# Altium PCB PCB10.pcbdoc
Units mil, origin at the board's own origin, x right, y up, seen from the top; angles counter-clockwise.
Board outline 3030 x 1495.29 mil, 6 copper layers (Top Layer, GND, Inner2, Inner3, 3.3, Bottom Layer); 71 components, 90 nets, 326 pads, 205 vias.
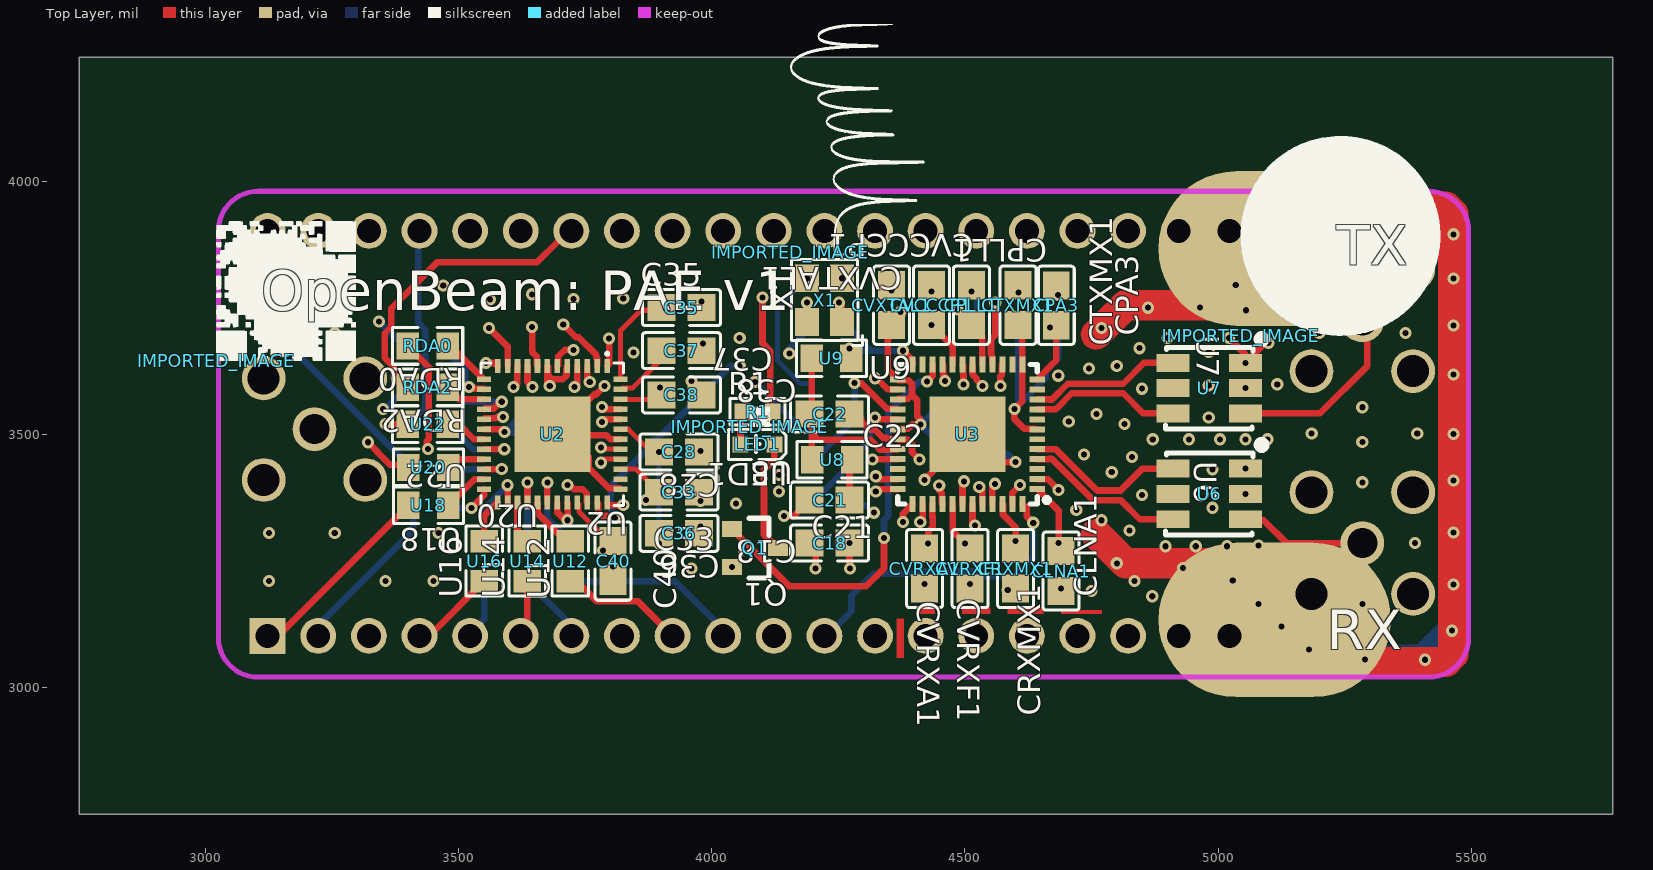
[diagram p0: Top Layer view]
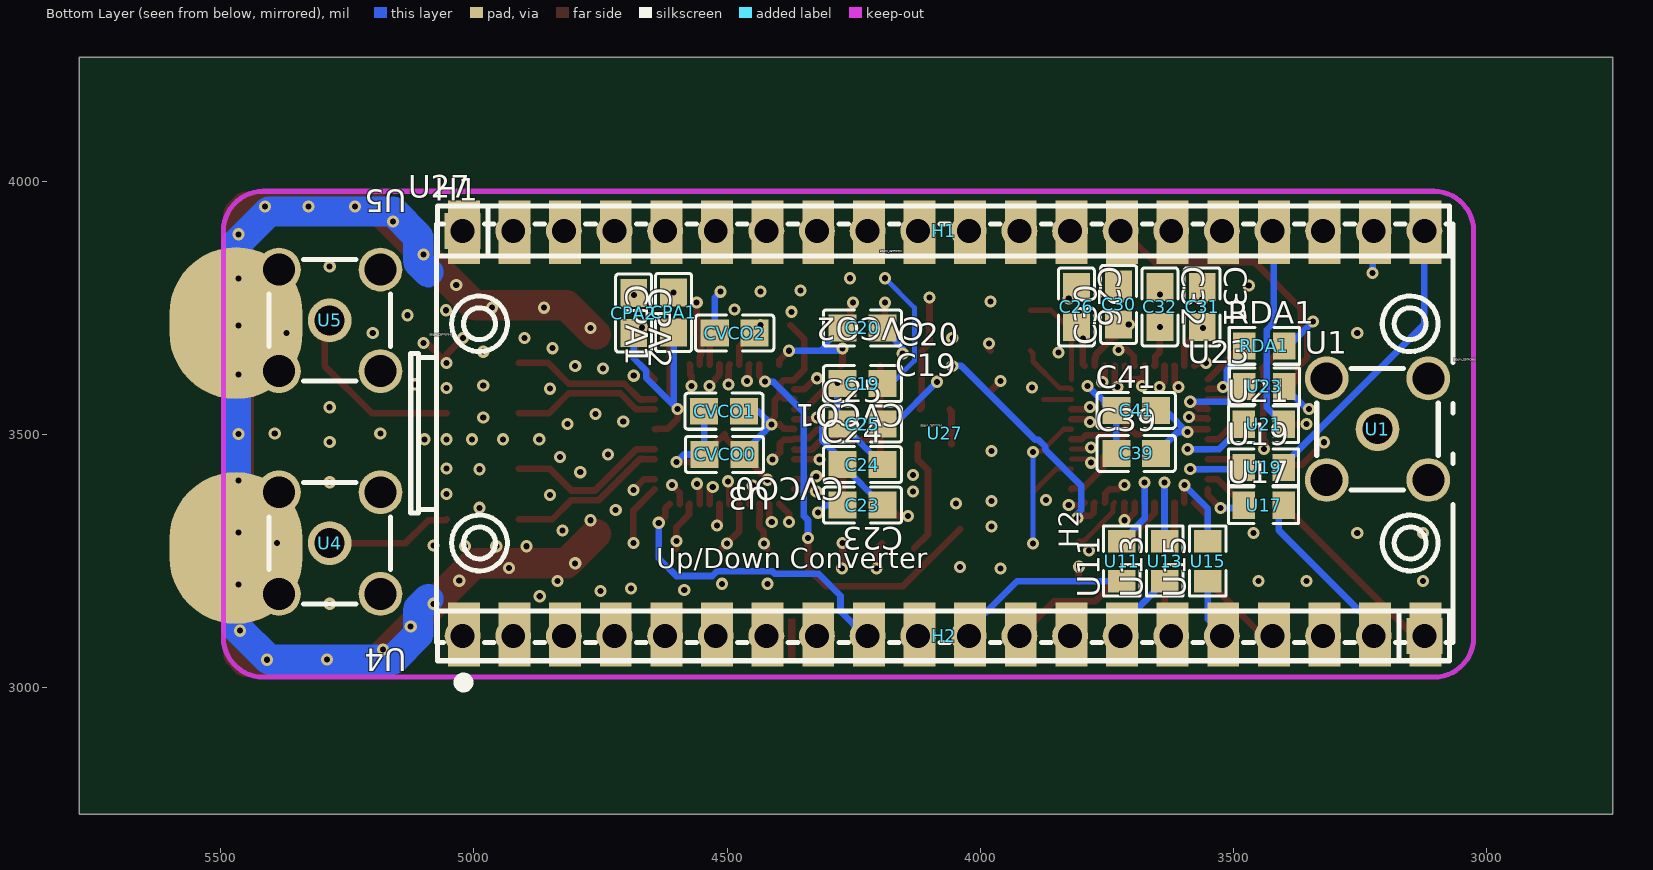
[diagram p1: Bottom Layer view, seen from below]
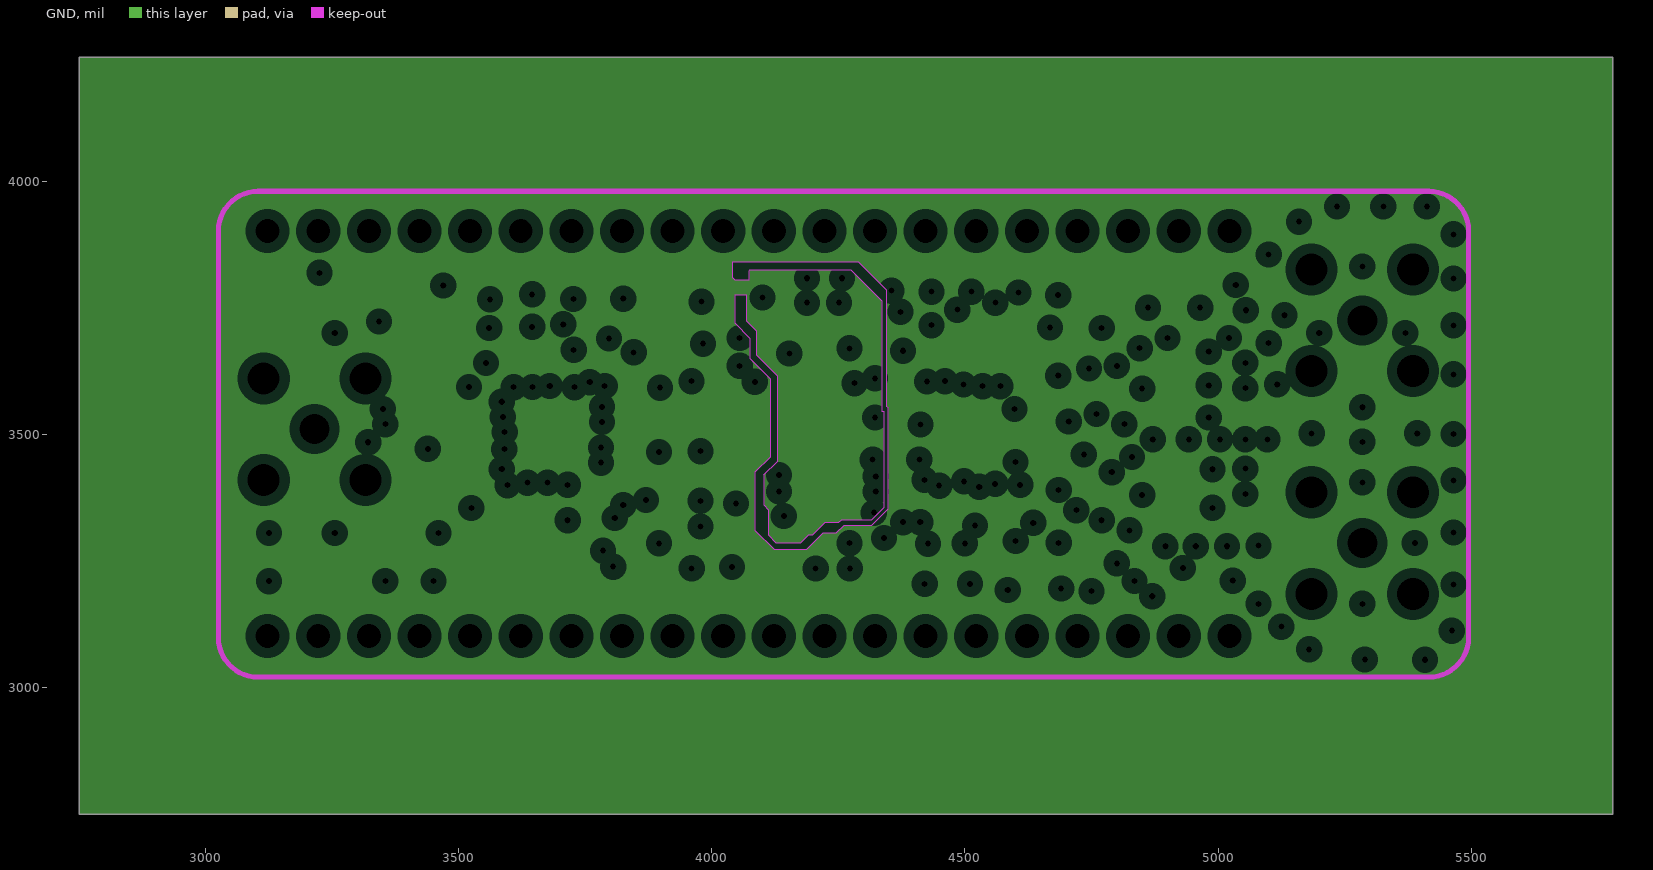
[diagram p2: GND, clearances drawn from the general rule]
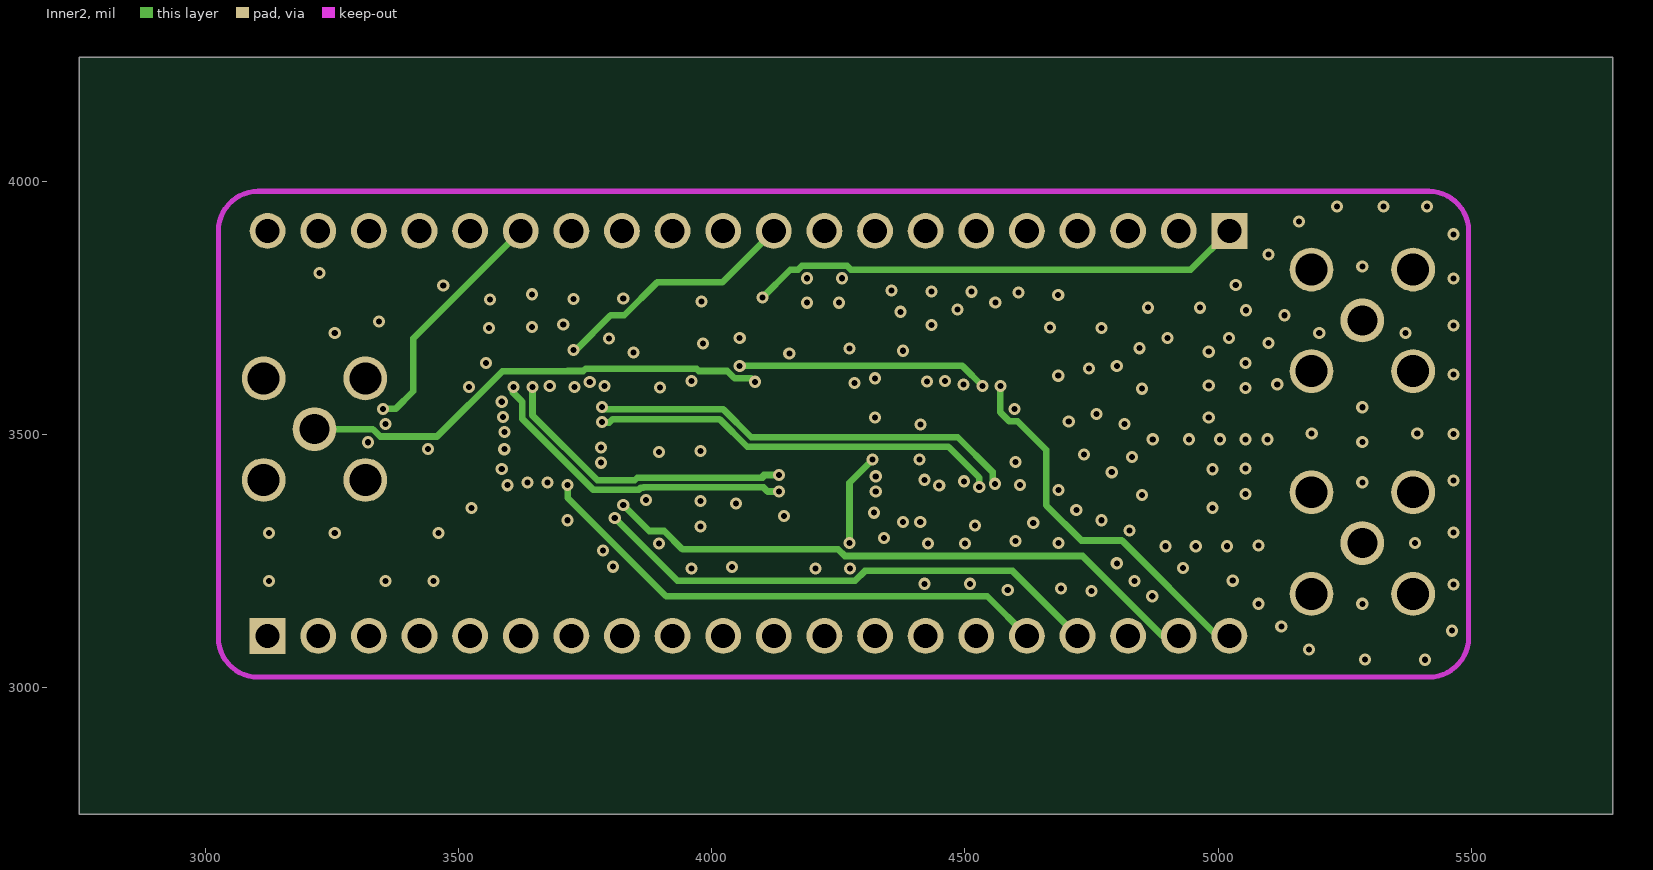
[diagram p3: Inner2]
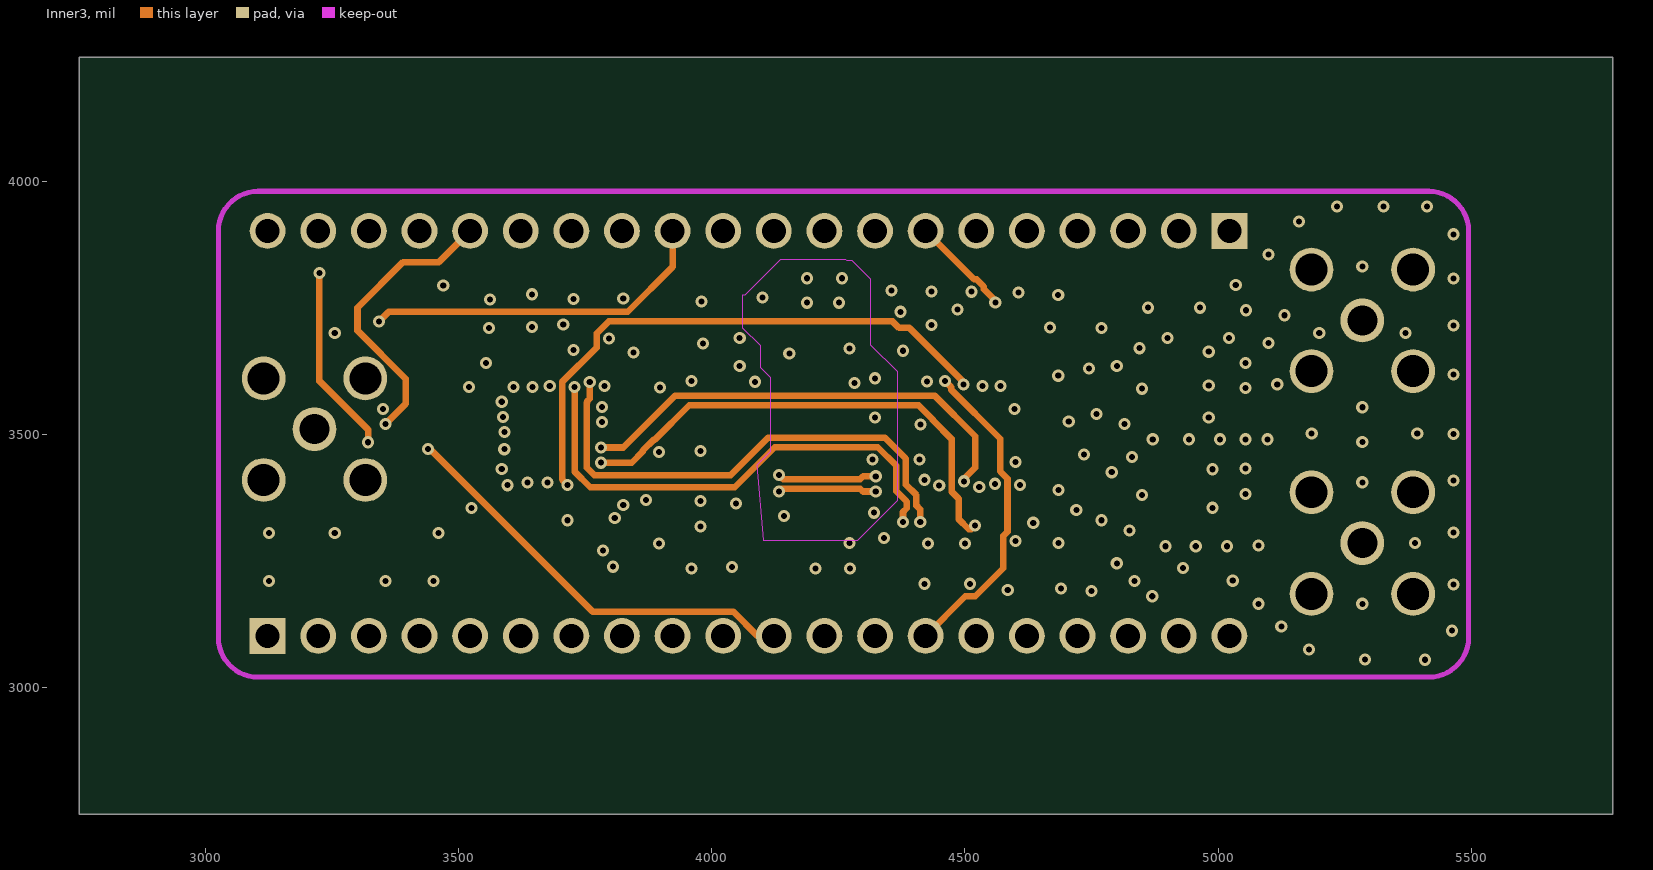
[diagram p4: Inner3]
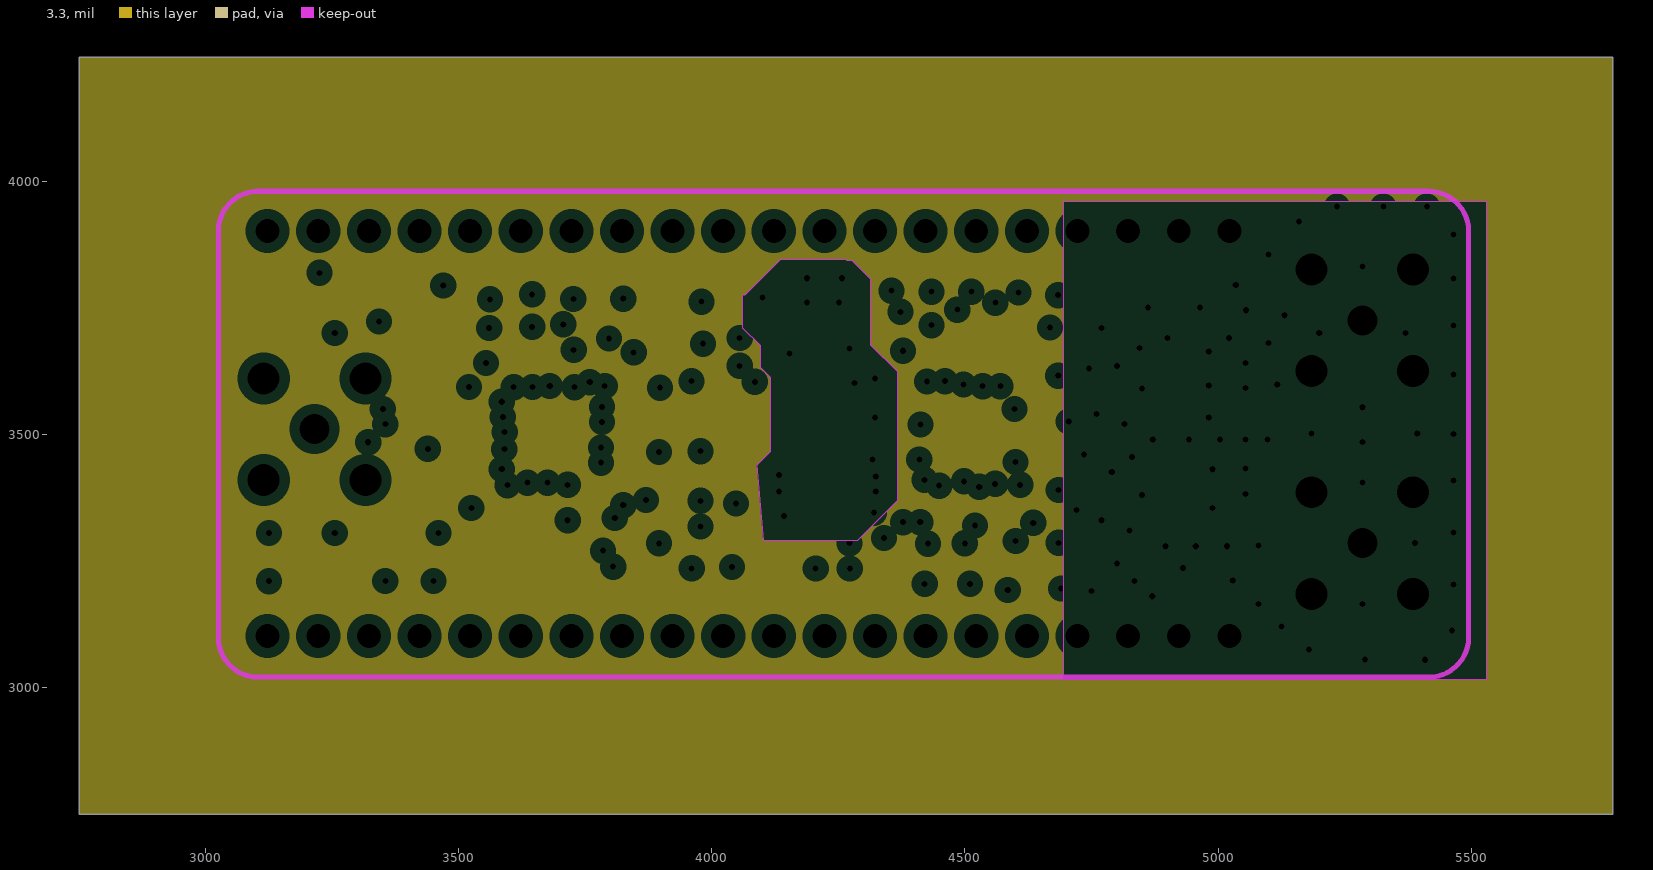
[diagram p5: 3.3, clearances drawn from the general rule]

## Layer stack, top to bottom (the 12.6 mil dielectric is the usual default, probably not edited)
Top Layer: signal copper (thickness not stored)
Dielectric: dielectric 12.6, FR-4, Dk 4.8
GND: plane copper (thickness not stored)
Dielectric: dielectric 12.6, FR-4, Dk 4.8
Inner2: signal copper (thickness not stored)
Dielectric: dielectric 12.6, FR-4, Dk 4.8
Inner3: signal copper (thickness not stored)
Dielectric: dielectric 12.6, FR-4, Dk 4.8
3.3: plane copper (thickness not stored)
Dielectric: dielectric 12.6, FR-4, Dk 4.8
Bottom Layer: signal copper (thickness not stored)

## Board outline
5780,2750 2750,2750 2750,4245.29 5780,4245.29

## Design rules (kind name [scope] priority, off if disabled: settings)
BoardOutlineClearance copperThickness1oz [All] p0: genericclearance=10 ignorepadtopadclearanceinfootprint=FALSE except(0: Arc-SplitContinuation Track-SplitContinuation SMDPad-SplitContinuation THPad-SplitContinuation Via-SplitContinuation Fill-SplitContinuation Poly-SplitContinuation Region-SplitContinuation Text-SplitContinuation; 6: Track-CutoutEdge SMDPad-CutoutEdge THPad-CutoutEdge Via-CutoutEdge Region-CutoutEdge; 11.8: Track-OutlineEdge SMDPad-OutlineEdge THPad-OutlineEdge Via-OutlineEdge Fill-OutlineEdge Region-OutlineEdge Poly-OutlineEdge Text-OutlineEdge Fill-CutoutEdge)
BoardOutlineClearance copperThickness2oz [All] p0: genericclearance=10 ignorepadtopadclearanceinfootprint=FALSE except(0: Arc-SplitContinuation Track-SplitContinuation SMDPad-SplitContinuation THPad-SplitContinuation Via-SplitContinuation Fill-SplitContinuation Poly-SplitContinuation Region-SplitContinuation Text-SplitContinuation; 6: Track-CutoutEdge SMDPad-CutoutEdge THPad-CutoutEdge Via-CutoutEdge Region-CutoutEdge; 11.8: Track-OutlineEdge SMDPad-OutlineEdge THPad-OutlineEdge Via-OutlineEdge Fill-OutlineEdge Region-OutlineEdge Poly-OutlineEdge Text-OutlineEdge Fill-CutoutEdge)
Clearance copperThickness1oz [(InNet('$1I297\BYPASS') OR InNet('GND') OR InNet('$1I297\XTAL') OR InNet('$1I297\$1N2490') OR InNet('$1I297\CPOUT') OR InNet('$1I297\$1N1515') OR InNet('$1I297\TUNE') OR InNet('$1I297\$1N2254') OR InNet('3.3') OR InNet('$1I297\D6') OR InNet('$1I297\RXP') OR InNet('$1I297\RXN') OR InNet('$1I297\D7') OR InNet('$1I297\D3') OR InNet('$1I297\TXP') OR InNet('$1I297\TXN') OR InNet('$1I297\D2') OR InNet('$1I297\D4') OR InNet('$1I297\D5') OR InNet('$1I297\D1') OR InNet('$1I297\$1N1513') OR InNet('$1I297\$1N1514') OR InNet('+5V') OR InNet('$1I61\$1N1654') OR InNet('$1I61\$1N1653') OR InNet('$1I61\$1N1602') OR InNet('$1I61\$1N1651') OR InNet('$1I61\$1N1648') OR InNet('$1I61\$1N1645') OR InNet('$1I61\$1N1642') OR InNet('$1I61\$1N1639') OR InNet('$1I61\$1N1636') OR InNet('$1I61\$1N1633') OR InNet('$1I61\$1N1662') OR InNet('$1I61\$1N1628') OR InNet('$1I61\$1N1625') OR InNet('$1I61\$1N1620') OR InNet('$1I61\$1N1617') OR InNet('$1I61\$1N1614') OR InNet('$1I61\$1N1611') OR InNet('$1I61\$1N1608') OR InNet('$1I61\$1N1605') OR InNet('RXQN') OR InNet('RXQP') OR InNet('RXIN') OR InNet('RXIP') OR InNet('TXQN') OR InNet('TXQP') OR InNet('TXIN') OR InNet('TXIP') OR InNet('$1N2410') OR InNet('$1N2400') OR InNet('$1N2396') OR InNet('$1N2392') OR InNet('$1N2390') OR InNet('$1N2388') OR InNet('$1N2386') OR InNet('$1N2382') OR InNet('$1N2430') OR InNet('$1N2428') OR InNet('$1N2374') OR InNet('$1N2420') OR InNet('$1N2372') OR InNet('$1N2366') OR InNet('$1N2356') OR InNet('$1N2426') OR InNet('$1N2424') OR InNet('$1N2378') OR InNet('$1N4497') OR InNet('$1N2418') OR InNet('$1N4492') OR InNet('$1N4646') OR InNet('$1N4593') OR InNet('BBC_DA7') OR InNet('BBC_DA6') OR InNet('BBC_DA5') OR InNet('BBC_DA4') OR InNet('BBC_DA3') OR InNet('BBC_DA2') OR InNet('BBC_DA1') OR InNet('BBC_DA0') OR InNet('BBC_DD7') OR InNet('BBC_DD6') OR InNet('BBC_DD5') OR InNet('BBC_DD4') OR InNet('BBC_DD3') OR InNet('BBC_DD2') OR InNet('BBC_DD1') OR InNet('BBC_DD0') OR InNet('BBC_CLK'))] p1: gap=7 ignorepadtopadclearanceinfootprint=FALSE except(4: Track-Track; 6: Track-SMDPad SMDPad-SMDPad Track-THPad SMDPad-THPad THPad-THPad Track-Via SMDPad-Via THPad-Via Via-Via SMDPad-Fill THPad-Fill Via-Fill Fill-Fill Track-Region SMDPad-Region THPad-Region Via-Region Region-Region Track-Poly SMDPad-Poly THPad-Poly Via-Poly Fill-Poly Region-Poly Poly-Poly Track-Text SMDPad-Text THPad-Text Via-Text Fill-Text Region-Text Poly-Text Text-Text; 6.9: Track-Hole SMDPad-Hole THPad-Hole Via-Hole Fill-Hole Region-Hole Poly-Hole Text-Hole Sheet-Hole; 11.8: Track-Fill Fill-Region Track-Sheet SMDPad-Sheet THPad-Sheet Via-Sheet Fill-Sheet Region-Sheet Poly-Sheet Text-Sheet)
Clearance copperThickness2oz [All] p1: gap=7 ignorepadtopadclearanceinfootprint=FALSE except(6: Track-SMDPad SMDPad-SMDPad Track-THPad SMDPad-THPad THPad-THPad Track-Via SMDPad-Via THPad-Via Via-Via SMDPad-Fill THPad-Fill Via-Fill Fill-Fill Track-Region SMDPad-Region THPad-Region Via-Region Region-Region Track-Poly SMDPad-Poly THPad-Poly Via-Poly Fill-Poly Region-Poly Poly-Poly Track-Text SMDPad-Text THPad-Text Via-Text Fill-Text Region-Text Poly-Text Text-Text; 6.9: Track-Hole SMDPad-Hole THPad-Hole Via-Hole Fill-Hole Region-Hole Poly-Hole Text-Hole Sheet-Hole; 8: Track-Track; 11.8: Track-Fill Fill-Region Track-Sheet SMDPad-Sheet THPad-Sheet Via-Sheet Fill-Sheet Region-Sheet Poly-Sheet Text-Sheet)
DiffPairsRouting differentialPair [All] p1: maxuncoupledlength=10 minlimit=6 maxlimit=6 mostfreqgap=6 toplayer_minwidth=5 toplayer_prefwidth=10 toplayer_maxwidth=100 bottomlayer_minwidth=5 bottomlayer_prefwidth=10 bottomlayer_maxwidth=100 midlayer2_minwidth=5 midlayer2_prefwidth=10 midlayer2_maxwidth=100 midlayer3_minwidth=5 midlayer3_prefwidth=10 midlayer3_maxwidth=100
PasteMaskExpansion pasteMaskExpansion [All] p1: expansion=0
PlaneConnect innerPlane [All] p1: planeconnectstyle=Relief reliefexpansion=20 reliefentries=4 reliefconductorwidth=10 reliefairgap=10
PolygonConnect copperRegion [All] p1: connectstyle=Relief reliefentries=4 reliefconductorwidth=10 polygonreliefangle="90 Angle" airgapwidth=10
RoutingVias viaSize [All] p1: viastyle="Through Hole" holewidth=12.0078 minholewidth=11.811 maxholewidth=248.0314 width=24.0158 minwidth=19.685 maxwidth=393.7008
SolderMaskExpansion solderMaskExpansion [All] p1: useseparateexpansions=TRUE expansion=2 expansionbottom=2
Width copperThickness1oz [All] p1: maxlimit=100 minlimit=5 preferedwidth=10
Width copperThickness2oz [All] p1: maxlimit=100 minlimit=8 preferedwidth=10

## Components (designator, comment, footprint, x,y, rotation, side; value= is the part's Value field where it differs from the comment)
C18 "CAP_0603" C0805 4232.57,3285.19 r0 top
C19 "CAP_0603" C0805 4232.57,3600.19 r0 bottom
C20 "CAP_0603" C0805 4232.57,3710.19 r0 bottom
C21 "CAP_0603" C0805 4232.57,3370.19 r0 top
C22 "CAP_0603" C0805 4232.57,3540.19 r180 top
C23 "CAP_0603" C0805 4232.57,3360.19 r0 bottom
C24 "CAP_0805" C0805 4232.57,3440.19 r180 bottom
C25 "CAP_0805" C0805 4232.57,3520.19 r180 bottom
C26 "CAP_0805" C0805 3809.94,3751.74 r270 bottom
C28 "CAP_0805" C0805 3935,3465.29 r180 top
C30 "CAP_0805" C0805 3726.35,3756.74 r90 bottom
C31 "CAP_0805" C0805 3561.3,3751.74 r270 bottom
C32 "CAP_0805" C0805 3644.94,3751.74 r270 bottom
C33 "CAP_0805" C0805 3935,3385.76 r0 top
C35 "CAP_0805" C0805 3940,3750.29 r0 top
C36 "CAP_0805" C0805 3935,3304.63 r180 top
C37 "CAP_0805" C0805 3940,3665.29 r180 top
C38 "CAP_0805" C0805 3940,3578.02 r180 top
C39 "CAP_0805" C0805 3691.63,3462.39 r180 bottom
C40 "CAP_0805" C0805 3804.94,3249.63 r90 top
C41 "CAP_0805" C0805 3691.63,3547.39 r180 bottom
CLNA1 "CAP_0603" C0805 4690,3229.93 r270 top
CPA1 "CAP_0603" C0805 4605.63,3740.92 r90 bottom
CPA2 "CAP_0603" C0805 4684.37,3739.66 r90 bottom
CPA3 "CAP_0603" C0805 4680.36,3754.93 r90 top
CPLL1 "CAP_0603" C0805 4512.68,3755.29 r90 top
CRXMX1 "CAP_0603" C0805 4600.12,3234.93 r270 top
CTXMX1 "CAP_0603" C0805 4605,3755.29 r90 top
CVCCCP1 "CAP_0603" C0805 4433.84,3755.29 r90 top
CVCO0 "CAP_0603" C0805 4505,3460.29 r0 bottom
CVCO1 "CAP_0603" C0805 4505.94,3545.74 r0 bottom
CVCO2 "CAP_0603" C0805 4485,3700.29 r0 bottom
CVRXA1 "CAP_0603" C0805 4420.36,3234.93 r270 top
CVRXF1 "CAP_0603" C0805 4510.24,3234.93 r270 top
CVXTAL1 "CAP_0603" C0805 4355,3755.29 r90 top
H1 "HDR-M_2.54_1x20P" HDR-TH_20P-P2.54-V-M-1 4072.38,3901.97 r180 bottom
H2 "HDR-M_2.54_1x20P" HDR-TH_20P-P2.54-V-M-1 4072.38,3101.97 r0 bottom
IMPORTED_IMAGE "IMPORTED_IMAGE" IMPORTED_IMAGE 5045,3695.24 r0 top
IMPORTED_IMAGE "IMPORTED_IMAGE" IMPORTED_IMAGE 4155,3860.29 r0 top
IMPORTED_IMAGE "IMPORTED_IMAGE" IMPORTED_IMAGE 3021.28,3645.29 r0 top
IMPORTED_IMAGE "IMPORTED_IMAGE" IMPORTED_IMAGE 4075.01,3515.29 r0 top
LED1 "LED_0603-R" LED0603-R-RD 4090,3480.29 r180 top
Q1 "P_MOS" SOT-23_L2.9-W1.3-P1.90-LS2.4-BR 4085,3275.29 r180 top
R1 "Res_0603" R0603 4089.96,3544.43 r0 top
RDA0 "3R00" R0805 3438.53,3674.63 r180 top
RDA1 "3R00" R0805 3438.53,3674.63 r180 bottom
RDA2 "3R00" R0805 3438.53,3592.9 r180 top
U1 "MCX5.08-H5_C9900009324" SMA-TH_MCX5.08-H5 3215,3510.29 r180 bottom
U2 "MAX5864ETM+" QFN-48_L7.0-W7.0-P0.50-BL-EP5.1 3685,3500.29 r180 top
U3 "MAX2831ETM+T" TQFN-48_L7.0-W7.0-P0.50-TL-EP5.6 4505,3500.29 r180 top
U4 "MCX5.08-H5_C9900009324" SMA-TH_MCX5.08-H5 5285,3285.29 r0 bottom
U5 "MCX5.08-H5_C9900009324" SMA-TH_MCX5.08-H5 5285,3725.29 r0 bottom
U6 "TCM2-43X+" IND-SMD_6P-L4.1-W3.8-P1.27-TL 4982.57,3382.36 r270 top
U7 "TCM2-43X+" IND-SMD_6P-L4.1-W3.8-P1.27-TL 4982.57,3591.34 r270 top
U8 "SCR0805J1M" R0805 4237.57,3450.19 r0 top
U9 "SCR0805J1M" R0805 4236.31,3650.19 r0 top
U11 "3R00" R0805 3719.94,3249.63 r90 bottom
U12 "3R00" R0805 3719.94,3249.63 r90 top
U13 "3R00" R0805 3634.94,3249.63 r90 bottom
U14 "3R00" R0805 3634.94,3249.63 r90 top
U15 "3R00" R0805 3549.94,3249.63 r90 bottom
U16 "3R00" R0805 3549.94,3249.63 r90 top
U17 "3R00" R0805 3439.94,3359.63 r180 bottom
U18 "3R00" R0805 3439.94,3359.63 r180 top
U19 "3R00" R0805 3439.94,3434.63 r180 bottom
U20 "3R00" R0805 3439.94,3434.63 r180 top
U21 "3R00" R0805 3439.94,3519.63 r180 bottom
U22 "3R00" R0805 3438.53,3520.29 r180 top
U23 "3R00" R0805 3438.53,3594.63 r180 bottom
U27 "PICO" comm-smd_l51.0-w21.0-p2.54_sc0916 4057.38,3501.97 r180 bottom locked
X1 "SX3M40.000E20F30THN" OSC-SMD_4P-L3.2-W2.5-BL 4222.57,3765.19 r90 top

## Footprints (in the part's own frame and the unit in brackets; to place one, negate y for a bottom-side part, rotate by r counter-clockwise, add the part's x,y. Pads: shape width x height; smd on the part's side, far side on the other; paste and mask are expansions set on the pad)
C0805 [mm]
  rect 1.41x1.35 smd: 1(-1,0) 2(1,0)
  silkscreen extent -1.96,-0.9 1.96,0.9
comm-smd_l51.0-w21.0-p2.54_sc0916 [mm]
  rect 1.6x3.2 smd: 1(-24.445,-10.087) 2(-21.905,-10.087) 3(-19.365,-10.087) 4(-16.825,-10.087) 5(-14.285,-10.087) 6(-11.745,-10.087) 7(-9.205,-10.087) 8(-6.665,-10.087) 9(-4.125,-10.087) 10(-1.585,-10.087) 11(0.955,-10.087) 12(3.495,-10.087) 13(6.035,-10.087) 14(8.575,-10.087) 15(11.115,-10.087) 16(13.655,-10.087) 17(16.195,-10.087) 18(18.735,-10.087) 19(21.275,-10.087) 20(23.815,-10.087) 21(23.815,10.087) 22(21.275,10.087) 23(18.735,10.087) 24(16.195,10.087) 25(13.655,10.087) 26(11.115,10.087) 27(8.575,10.087) 28(6.035,10.087) 29(3.495,10.087) 30(0.955,10.087) 31(-1.585,10.087) 32(-4.125,10.087) 33(-6.665,10.087) 34(-9.205,10.087) 35(-11.745,10.087) 36(-14.285,10.087) 37(-16.825,10.087) 38(-19.365,10.087) 39(-21.905,10.087) 40(-24.445,10.087)
  silkscreen extent -27.11,-12.75 25.18,10.5
HDR-TH_20P-P2.54-V-M-1 [mm]
  rect 1.8x1.8 hole 1.2: 1(-24.13,0)
  round 1.8 hole 1.2: 2(-21.59,0) 3(-19.05,0) 4(-16.51,0) 5(-13.97,0) 6(-11.43,0) 7(-8.89,0) 8(-6.35,0) 9(-3.81,0) 10(-1.27,0) 11(1.27,0) 12(3.81,0) 13(6.35,0) 14(8.89,0) 15(11.43,0) 16(13.97,0) 17(16.51,0) 18(19.05,0) 19(21.59,0) 20(24.13,0)
  silkscreen extent -25.4,-1.25 25.4,1.25
IMPORTED_IMAGE [mil]
  silkscreen extent 0,0 394,394
IND-SMD_6P-L4.1-W3.8-P1.27-TL [mm]
  rect 0.9x1.657 smd: 1(-1.27,1.814) 2(0,1.814) 3(1.27,1.814) 4(1.27,-1.814) 5(0,-1.814) 6(-1.27,-1.814)
  silkscreen extent -2.66,-2.2 2.05,2.83
LED0603-R-RD [mm]
  rect 0.8x0.8 smd: 1(0.851,0) 2(-0.851,0)
  silkscreen extent -1.44,-0.75 1.44,0.75
OSC-SMD_4P-L3.2-W2.5-BL [mm]
  rect 1.4x1.2 smd: 1(-1.1,-0.875) 2(1.1,-0.875) 3(1.1,0.875) 4(-1.1,0.875)
  silkscreen extent -2.29,-1.9 2.03,1.65
QFN-48_L7.0-W7.0-P0.50-BL-EP5.1 [mm]
  rect 0.28x0.7 smd: 1(-2.75,-3.427) 2(-2.25,-3.427) 3(-1.75,-3.427) 4(-1.25,-3.427) 5(-0.75,-3.427) 6(-0.25,-3.427) 7(0.25,-3.427) 8(0.75,-3.427) 9(1.25,-3.427) 10(1.75,-3.427) 11(2.25,-3.427) 12(2.75,-3.427) 25(2.75,3.427) 26(2.25,3.427) 27(1.75,3.427) 28(1.25,3.427) 29(0.75,3.427) 30(0.25,3.427) 31(-0.25,3.427) 32(-0.75,3.427) 33(-1.25,3.427) 34(-1.75,3.427) 35(-2.25,3.427) 36(-2.75,3.427)
  rect 0.7x0.28 smd: 13(3.427,-2.75) 14(3.427,-2.25) 15(3.427,-1.75) 16(3.427,-1.25) 17(3.427,-0.75) 18(3.427,-0.25) 19(3.427,0.25) 20(3.427,0.75) 21(3.427,1.25) 22(3.427,1.75) 23(3.427,2.25) 24(3.427,2.75) 37(-3.427,2.75) 38(-3.427,2.25) 39(-3.427,1.75) 40(-3.427,1.25) 41(-3.427,0.75) 42(-3.427,0.25) 43(-3.427,-0.25) 44(-3.427,-0.75) 45(-3.427,-1.25) 46(-3.427,-1.75) 47(-3.427,-2.25) 48(-3.427,-2.75)
  rect 3.81x3.81 smd: 49(0,0)
  silkscreen extent -3.58,-4.11 3.58,3.58
R0603 [mil]
  rect 31.75x34.02 smd: 1(-29.66,0) 2(29.66,0)
  silkscreen extent -55,-26 55,26
R0805 [mm]
  rect 1.133x1.377 smd: 1(-1,0) 2(1,0)
  silkscreen extent -1.76,-0.92 1.76,0.92
SMA-TH_MCX5.08-H5 [mm]
  round 2.2 hole 1.6: 1(-2.55,-2.55) 2(-2.55,2.55) 3(2.55,2.55)
  round 2.2 hole 1.6 copper offset 0,0: 4(2.55,-2.55)
  round 2.2 hole 1.5: 5(0,0)
  silkscreen extent -3.05,-3.05 3.05,3.05
SOT-23_L2.9-W1.3-P1.90-LS2.4-BR [mm]
  rect 1x0.8 smd: 1(1.15,-0.95) 2(1.15,0.95) 3(-1.15,0)
  silkscreen extent -0.7,-1.5 0.7,1.5
TQFN-48_L7.0-W7.0-P0.50-TL-EP5.6 [mm]
  rect 0.8x0.3 smd: 1(-3.5,2.751) 2(-3.5,2.25) 3(-3.5,1.75) 4(-3.5,1.251) 5(-3.5,0.75) 6(-3.5,0.251) 7(-3.5,-0.249) 8(-3.5,-0.749) 9(-3.5,-1.25) 10(-3.5,-1.75) 11(-3.5,-2.249) 12(-3.5,-2.748) 25(3.5,-2.748) 26(3.5,-2.249) 27(3.5,-1.75) 28(3.5,-1.25) 29(3.5,-0.749) 30(3.5,-0.249) 31(3.5,0.251) 32(3.5,0.75) 33(3.5,1.251) 34(3.5,1.75) 35(3.5,2.25) 36(3.5,2.751)
  rect 0.3x0.8 smd: 13(-2.751,-3.5) 14(-2.251,-3.5) 15(-1.75,-3.5) 16(-1.25,-3.5) 17(-0.749,-3.5) 18(-0.25,-3.5) 19(0.249,-3.5) 20(0.749,-3.5) 21(1.25,-3.5) 22(1.75,-3.5) 23(2.251,-3.5) 24(2.751,-3.5) 37(2.751,3.5) 38(2.251,3.5) 39(1.75,3.5) 40(1.25,3.5) 41(0.749,3.5) 42(0.25,3.5) 43(-0.25,3.5) 44(-0.749,3.5) 45(-1.25,3.5) 46(-1.75,3.5) 47(-2.251,3.5) 48(-2.751,3.5)
  rect 3.81x3.81 smd: 49(0,0.001)
  silkscreen extent -4.11,-3.5 3.5,3.5

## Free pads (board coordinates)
  oval 459.18x305.43 smd: 50(5111.88,3867.17) 51(5111.88,3133.41)
  oval 263.43x299.99 smd far side: 52(5470,3719.82) 53(5470,3275.53)

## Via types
v1: diameter 24.02, hole 12.01, Top Layer to Bottom Layer, 189 vias
v2: diameter 24, hole 12, Top Layer to Bottom Layer, 16 vias

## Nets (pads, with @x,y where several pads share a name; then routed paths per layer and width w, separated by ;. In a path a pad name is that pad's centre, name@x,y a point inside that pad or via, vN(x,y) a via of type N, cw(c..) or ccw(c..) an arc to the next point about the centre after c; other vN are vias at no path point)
3.3: C28.2 C30.1 C31.2 C32.2 C33.1 C36.2 C38.2 C39.2 C40.2 C41.2 CLNA1.1 CPA1.1 CPA2.1 CPA3.1 CPLL1.1 CRXMX1.1 CTXMX1.1 CVCCCP1.1 CVCO0.1 CVCO1.1 CVCO2.1 CVRXA1.1 CVRXF1.1 CVXTAL1.1 H1.5 U2.2 U2.8 U2.11 U2.18 U2.33 U2.39 U2.43 U2.46 U3.1 U3.7 U3.12 U3.13 U3.17 U3.20 U3.25 U3.27 U3.30 U3.39 U3.40 U3.41 U3.46 U27.36 X1.4 | length 2894.8
  Top Layer w10: U2.33 3737.4,3362.16 3737.4,3347.02 3795.43,3289 C40.2 ; U2.39 3850,3431.39 C33.1 ; U2.43 3835.09,3510.13 3878.32,3466.89 3895.63,3466.89 v1(3895.63,3465.29) ; U2.46 C38.2@3874.46,3569.19
  Top Layer w12.99: U2.18 3576.84,3510.13 3576.96,3510.01 3585.37,3510.01 v1(3590.67,3504.71) ; v1(3560,3710.29) 3596.42,3673.87 U2.11 ; v1(3644.94,3712.37) 3644.94,3663.02 3653.78,3654.18 3653.78,3636.92 U2.8 ; v1(3706.35,3717.37) 3732.23,3691.49 3737.14,3691.49 3771.89,3656.74 3771.89,3651.83 3773.58,3650.14 U2.2 ; U3.27 4368.47,3570.46 4388.12,3570.46 4395.43,3577.77 ; U3.25 4368.47,3607.23 4388.12,3607.23 4395.43,3599.92 4395.43,3577.77 ; v2(4412.01,3519.51) 4412.01,3529.51 4405.43,3536.09 4405.43,3567.77 4395.43,3577.77
  Top Layer w13: v1(4187.86,3760.2) 4188.12,3759.94 X1.4 ; U3.30 4368.52,3511.4 4388.12,3511.4 4396.23,3519.51 v2(4412.01,3519.51) ; U3.25 4347.57,3628.13 4347.57,3688.49 CVXTAL1.1@4375,3715.92 ; CVRXA1.1 4420.36,3277.38 v1(4427.15,3284.17) 4427.15,3307.6 4436.1,3316.56 4436.1,3336.85 4435.36,3337.6 4435.36,3361.75 U3.39 ; v1(4433.84,3715.92) 4475.49,3674.26 U3.20 ; v1(4449.08,3398.68) 4449.08,3388.83 4454.49,3383.41 4454.49,3363.79 U3.40 ; U3.41 4475.49,3309.05 v1(4499.81,3284.73) CVRXF1.1 ; CPLL1.1 4534.51,3694.09 U3.17 ; U3.46 4575.22,3361.17 4575.22,3341.58 4600.12,3316.67 v1(4600.12,3289.25) CRXMX1.1 ; CTXMX1.1 4613.3,3707.62 U3.13 4613.3,3565.41 v2(4597.98,3550.09) 4597.8,3549.91 4597.8,3530.49 4616.88,3511.4 4636.48,3511.4 4637.8,3510.09 U3.7 ; U3.1 4685,3349.79 v1(4685,3285.6) ; U3.12 4659.86,3625.56 4659.86,3626.08 4674.21,3640.43 4674.73,3640.43 4680.36,3646.06 CPA3.1
  Bottom Layer w10: v1(3895.63,3284.63) v1(3895.63,3465.29)
  Bottom Layer w12.99: v1(3560,3710.29) 3561.3,3711.59 C31.2 ; C39.2 3609.94,3504.71 v1(3590.67,3504.71) 3595.97,3510.01 3597.24,3510.01 3611.59,3524.36 3611.59,3525.63 3633.35,3547.39 C41.2 ; v2(4412.01,3519.51) 4465.63,3465.89 CVCO0.1
  Bottom Layer w13: v2(4412.01,3519.51) 4438.24,3545.74 CVCO1.1 ; v2(4597.98,3550.09) v2@4605.63,3557.75 ; CPA1.1 v2@4605.63,3557.75 ; CPA2.1@4674.12,3705.04 CPA2.1@4684.37,3715.29 ; CPA2.1 4684.37,3650.6 4659.86,3626.08 4659.86,3611.97 v2@4605.63,3557.75
  other v1: 3785,3270.29 3870,3370.29 3897.58,3592.32 4667.93,3711.23 4372.8,3742.13 4485,3746.43
$1I61\$1N1602: C37.2 U2.47 | length 121.8
  Top Layer w10: U2.47 3823.13,3592.06 3843.54,3592.06 3895.63,3644.16 3895.63,3660.29 C37.2
$1I61\$1N1605: U2.30 U11.2 | length 173.5
  Top Layer w13: U2.30 v1(3675.16,3404.63)
  Bottom Layer w13: v1(3675.16,3404.63) 3675.16,3333.77 U11.2
$1I61\$1N1608: U2.29 U12.2 | length 108.5
  Top Layer w13: U2.29 3655.47,3344.09 3710.57,3289 U12.2
$1I61\$1N1611: U2.28 U13.2 | length 155.3
  Top Layer w13: U2.28 v1(3635.79,3404.63)
  Bottom Layer w13: U13.2 3635.79,3289.85 v1(3635.79,3404.63)
$1I61\$1N1614: U2.27 U14.2 | length 84.2
  Top Layer w13: U2.27 3616.1,3307.83 U14.2
$1I61\$1N1617: U2.26 U15.2 | length 164.2
  Top Layer w13: U2.26 v1(3596.42,3399.63)
  Bottom Layer w13: U15.2 3549.94,3353.14 v1(3596.42,3399.63)
$1I61\$1N1620: U2.25 U16.2 | length 87.5
  Top Layer w13: U16.2 3549.94,3338.56 U2.25
$1I61\$1N1625: U2.24 U17.1 | length 95.5
  Top Layer w13: v1(3524.94,3354.63) 3550.06,3379.75 U2.24
  Bottom Layer w13: U17.1 3484.31,3354.63 v1(3524.94,3354.63)
$1I61\$1N1628: U2.23 U18.1 | length 92.3
  Top Layer w13: U18.1 3531.39,3411.71 U2.23
$1I61\$1N1633: U2.21 U20.1 | length 75.5
  Top Layer w13: U20.1@3479.31,3439.63 3490.76,3451.08 U2.21
$1I61\$1N1636: U2.20 U21.1 | length 170.7
  Top Layer w13: U2.20 v1(3589.94,3470.76)
  Bottom Layer w13: U21.1 3528.17,3470.76 v1(3589.94,3470.76)
$1I61\$1N1639: U2.19 U22.1 | length 84.5
  Top Layer w13: U22.1 3499.94,3520.29 3529.78,3490.45 U2.19
$1I61\$1N1642: U2.16 U23.1 | length 160.6
  Top Layer w13: U2.16 3551.75,3551.19 3569.01,3551.19 3582.32,3564.5 v1(3584.94,3564.5)
  Bottom Layer w13: U23.1 3508.03,3564.5 v1(3584.94,3564.5)
$1I61\$1N1645: RDA2.1 U2.15 | length 82
  Top Layer w13: RDA2.1 3501.62,3569.19 U2.15
$1I61\$1N1648: RDA1.1 U2.14 | length 130.3
  Top Layer w13: v1(3520.23,3593.65) 3528.02,3593.65 3531.11,3590.56 3548.37,3590.56 U2.14
  Bottom Layer w13: RDA1.1 3477.9,3661.68 3512.68,3626.9 3512.68,3601.2 v1(3520.23,3593.65)
$1I61\$1N1651: RDA0.1 U2.13 | length 99.5
  Top Layer w13: RDA0.1 3483.99,3674.63 U2.13
$1I61\$1N1653: C35.1 U2.48 | length 194
  Top Layer w10: U2.48 3819.94,3705.23 3860,3745.29 C35.1@3900.63,3745.29
$1I61\$1N1654: C26.2 U2.1 | length 55.7
  Top Layer w12.99: U2.1 3796.95,3638.91 v1(3796.95,3689.38)
$1I61\$1N1662: U2.22 U19.1 | length 143.9
  Top Layer w13: U2.22 v1(3584.94,3431.39)
  Bottom Layer w13: U19.1@3479.31,3439.63 3487.54,3431.39 v1(3584.94,3431.39)
$1I297\$1N1513: U4.5 U6.3 | length 250.5
  Top Layer w13: U6.3 5056.04,3330.29 5090,3330.29 5134.99,3285.29 U4.5
$1I297\$1N1514: U5.5 U7.3 | length 374.1
  Top Layer w13: U7.3 5201.05,3541.34 5295,3635.29 5295,3715.29 U5.5
$1I297\$1N1515: C21.2 U8.2 | length 85
  Top Layer w13: C21.2 U8.2@4271.94,3455.19
$1I297\$1N2254: C23.1 C24.1 U3.29 | length 272.8
  Top Layer w13: v1(4322.3,3533.23) 4325.74,3529.79 U3.29
  Bottom Layer w13: C23.1 4271.94,3438.93 C24.1 4271.94,3448.21 4312.18,3488.45 4312.18,3523.11 v1(4322.3,3533.23)
$1I297\$1N2490: C19.1 X1.3 | length 269.2
  Bottom Layer w10: v1(4188.12,3808.5) 4130,3750.39 4130,3645.29 4175.09,3600.19 C19.1
$1I297\BYPASS: C18.2 U3.33 | length 284.1
  Top Layer w13: v1(4271.94,3285.19) 4271.94,3235.82 v2(4272.57,3235.19) ; v2(4317.68,3450.19) 4318.53,3451.04 U3.33
  Inner2 w13: v1(4271.94,3285.19) 4271.94,3404.45 v2(4317.68,3450.19)
$1I297\CPOUT: C20.2 U3.24 U9.2 | length 242.5
  Top Layer w13: v1(4271.94,3669.88) 4271.94,3638.93 U9.2@4275.68,3635.19 ; v2(4377.57,3665.19) 4396.69,3646.07 U3.24
  Bottom Layer w10: C20.2 4316.94,3665.19
  Bottom Layer w13: v1(4271.94,3669.88) 4276.62,3665.19 4316.94,3665.19 v2(4377.57,3665.19)
$1I297\D1: U3.23
$1I297\D2: U3.11
$1I297\D3: U3.8
$1I297\D4: U3.34
$1I297\D5: U3.14
$1I297\D6: U3.3
$1I297\D7: U3.6
$1I297\RXN: U3.5 U6.6 | length 320
  Top Layer w13: U3.5 4665.04,3470.74 4665.39,3470.39 4679.76,3470.39 4760.96,3389.19 4807.57,3389.19 4850.73,3432.36 U6.6
$1I297\RXP: U3.4 U6.4 | length 317.8
  Top Layer w13: U3.4 4665.04,3451.04 4665.39,3451.39 4671.89,3451.39 4753.09,3370.19 4807.57,3370.19 4845.4,3332.36 U6.4
$1I297\TUNE: C22.2 U3.32 U8.1 U9.1 | length 366.2
  Top Layer w13: U8.1@4193.2,3455.19 4196.94,3458.93 4196.94,3502.79 ; U9.1@4196.94,3635.19 4196.94,3502.79 ; U3.32 4365.89,3469.43 4333.06,3469.43 4312.71,3489.79 4209.94,3489.79 4196.94,3502.79
$1I297\TXN: U3.10 U7.6 | length 298.5
  Top Layer w13: U3.10 4665.04,3569.19 4665.39,3568.84 4671.89,3568.84 4703.24,3600.19 4812.57,3600.19 4853.71,3641.34 U7.6
$1I297\TXP: U3.9 U7.4 | length 298
  Top Layer w13: U3.9 4665.04,3549.49 4665.39,3549.84 4679.76,3549.84 4711.11,3581.19 4812.57,3581.19 4852.42,3541.34 U7.4
$1I297\XTAL: C19.2 C24.2 C25.1 U3.28 | length 304.5
  Top Layer w12.99: v1(4281.94,3601.22) 4295.88,3601.22 4346.29,3550.81 4365.89,3550.81 U3.28
  Bottom Layer w12.99: C25.1 4281.94,3530.19 v1(4281.94,3601.22)
  Bottom Layer w13: C24.2 4271.94,3518.93 C25.1
$1N2356: H2.3 U27.18
$1N2366: H2.8 U27.13
$1N2372: H2.13 U27.8
$1N2374: H2.18 U27.3
$1N2378: H1.2 U27.39
$1N2382: H1.4 U27.37
$1N2386: H1.6 U27.35
$1N2388: H1.7 U3.16 U27.34 | length 327.9
  Top Layer w13: U3.16 4554.19,3652.53 4552.89,3653.83 ccw(c4540.41,3653.83) 4551.52,3659.53 4551.52,3685.85 ccw(c4539.25,3688.16) 4551.74,3688.16 4560,3696.43 v1(4560,3760.29)
  Inner3 w13: H1.7 4517.99,3806.35 4522.82,3806.35 4537.17,3792.01 4537.17,3787.18 4560,3764.35 v1(4560,3760.29)
$1N2390: H1.8 U27.33
$1N2392: C25.2 H1.9 U1.5 U27.32 | length 1085
  Inner2 w12.99: U1.5 3330.37,3510.28 3344.86,3495.8 3457.02,3495.8 3586.13,3624.92 3714.63,3624.92 3715,3625.29 3746.09,3625.29 3750.48,3629.68 3970.02,3629.68 3974.41,3625.29 4030.37,3625.29 4044.86,3610.8 4078.05,3610.8 v1(4085,3603.85)
  Bottom Layer w12.99: v1(4085,3603.85) 4168.66,3520.19 C25.2
$1N2396: H1.11 U27.30
$1N2400: H1.13 U27.28
$1N2410: H1.18 U27.23
$1N2418: H2.12 U3.48 U27.9 | length 617.7
  Top Layer w13: U3.48 4622.49,3353.3 4622.49,3337.8 v1(4635,3325.29)
  Bottom Layer w13: H2.12 4227.38,3101.97 4275.8,3150.4 4275.8,3181.09 4318.98,3224.27 4405.21,3224.27 4410.21,3229.27 4520.19,3229.27 4529.17,3220.29 4600,3220.29 4635,3255.29 v1(4635,3325.29)
$1N2420: H2.14 U3.21 U27.7 | length 667.6
  Top Layer w13: U3.21 4457.11,3636.77 4457.11,3617.17 4460.6,3613.67 v1(4460.6,3605.29)
  Inner3 w13: H2.14 4500.7,3180.29 4520.19,3180.29 4575.63,3235.73 4575.63,3299.39 4584.05,3307.81 4584.05,3412.47 4569.7,3426.81 4569.7,3491.32 4472.57,3588.45 4472.57,3593.32 v1(4460.6,3605.29)
$1N2424: H2.16 U2.34 U3.19 U27.5 | length 2270.5
  Top Layer w13: v1(3715,3400.29) 3718.96,3400.29 3727.64,3391.61 3744.89,3391.61 3752.92,3383.59 3752.92,3366.33 U2.34 ; U3.19 4496.47,3636.81 4496.47,3617.17 4497.06,3616.57 v1(4497.06,3598.59)
  Inner2 w13: v1(3715,3400.29) 3715,3374.93 3909.64,3180.29 4544.06,3180.29 H2.16
  Inner3 w13: v1(3715,3400.29) 3704.23,3411.06 3704.23,3603.42 3772.46,3671.64 3772.46,3699.52 3796.22,3723.29 4357,3723.29 4370,3710.29 4390.36,3710.29 4497.06,3603.59 v1(4497.06,3598.59)
$1N2426: H2.17 U2.35 U3.18 U27.4 | length 2055.5
  Top Layer w13: U2.35 3775.27,3363.66 3775.27,3346.4 3782.59,3339.09 3799.84,3339.09 3804.18,3334.74 v1(3808.15,3334.74) ; U3.18 4514.85,3620.43 4516.12,3619.17 4516.12,3617.17 4523.43,3609.85 4523.43,3606.86 v1(4535,3595.29)
  Inner2 w13: v1(3808.15,3334.74) 3932.18,3210.71 4282.71,3210.71 4302.29,3230.29 4594.06,3230.29 H2.17 ; v1(4055,3635.29) 4495,3635.29 v1(4535,3595.29)
  Bottom Layer w13: v1(3808.15,3334.74) 3808.15,3342.5 3800.51,3350.14 3800.51,3384.78 3800,3385.29 3800,3398.29 3871.14,3469.43 3871.14,3475.43 3885.49,3489.78 3891.49,3489.78 4037,3635.29 v1(4055,3635.29)
$1N2428: H2.19 U2.36 U27.2 | length 1238.2
  Top Layer w13: U2.36 3798.33,3360.29 v1(3825,3360.29)
  Inner2 w13: v1(3825,3360.29) 3876.17,3309.12 3905.78,3309.12 3942.21,3272.68 4249.82,3272.68 4262.82,3259.68 4732.43,3259.68 4890.14,3101.97 H2.19
$1N2430: H2.20 U3.15 U27.1 | length 795.7
  Top Layer w12.99: v1(4570,3595.29) 4570,3614.59 4572.58,3617.17 4572.58,3636.77 U3.15
  Inner2 w12.99: v1(4570,3595.29) 4570,3543.45 4587.84,3525.61 4604.31,3525.61 4660.51,3469.41 4660.51,3359.78 4730,3290.29 4810,3290.29 4998.32,3101.97 H2.20
$1N4492: Q1.1 U3.22 | length 813.3
  Top Layer w13: Q1.1 4152.13,3200.29 4305,3200.29 4340,3235.29 v1(4340,3295.29) ; v1(4425,3604.34) 4436.1,3615.45 U3.22
  Bottom Layer w13: v1(4340,3295.29) 4340,3330.65 4348.19,3338.84 4348.19,3543.48 4409.05,3604.34 v1(4425,3604.34)
$1N4497: H2.15 U27.6
$1N4593: LED1.2 Q1.3 | length 224.7
  Top Layer w13: LED1.2 4123.5,3450.34 4103.08,3429.92 4103.08,3302.48 Q1.3
$1N4646: LED1.1 R1.1 | length 70.7
  Top Layer w13: LED1.1 4056.5,3545.63 R1.1@4060.3,3549.43
+5V: H1.1 R1.2 U27.40 | length 1212.3
  Top Layer w13: v1(4100,3770.29) 4100,3680.29 4115,3665.29 4115,3554.05 R1.2@4119.62,3549.43
  Inner2 w13: v1(4100,3770.29) 4155,3825.29 4170.26,3825.29 4177.97,3833 4267.16,3833 4274.87,3825.29 4945.7,3825.29 H1.1
BBC_CLK: H1.10 U2.6 U27.31 | length 548.1
  Top Layer w13: U2.6 3696.53,3636.92 3696.53,3654.18 3709.35,3667 v1(3727,3667)
  Inner2 w13: v1(3727,3667) 3731.71,3667 3800,3735.29 3826.75,3735.29 3891.75,3800.29 4020.7,3800.29 H1.10
BBC_DA0: H2.11 RDA0.2 U27.10 | length 1061.1
  Top Layer w13: RDA0.2 3442.5,3631.29 3442.5,3629.56 3440.62,3627.68 3440.62,3490.51 3436.52,3486.41 3436.52,3473.81 v1(3439.02,3471.31)
  Inner3 w13: v1(3439.02,3471.31) 3442.89,3471.31 3764.31,3149.89 4042.23,3149.89 4090.14,3101.97 H2.11
BBC_DA1: H1.12 RDA1.2 U27.29 | length 772.6
  Inner3 w13: v1(3342.37,3722.92) 3361.31,3741.86 3760.48,3741.86 3761.03,3742.41 3833.87,3742.41 3922.38,3830.92 H1.12
  Bottom Layer w13: v1(3342.37,3722.92) 3390.66,3674.63 RDA1.2
BBC_DA2: H1.14 RDA2.2 U27.27 | length 620.7
  Top Layer w13: RDA2.2 3394.16,3597.9 3384.16,3597.9 3371.19,3610.88 3371.19,3633.79 3353.86,3651.12 3353.86,3699.77 3366.86,3712.77 3366.86,3749.38 3457.77,3840.29 3655,3840.29 3697.38,3882.67 3697.38,3901.97 3702.38,3906.97 3717.38,3906.97 H1.14
BBC_DA3: H1.15 U23.2 U27.26 | length 546.7
  Inner2 w13: v1(3350,3550.29) 3375,3550.29 3410,3585.29 3410,3689.59 H1.15
  Bottom Layer w13: v1(3350,3550.29) 3354.83,3550.29 U23.2
BBC_DA4: H1.16 U22.2 U27.25 | length 615.3
  Top Layer w13: v1(3355,3520.29) U22.2
  Inner3 w13: v1(3355,3520.29) 3395,3560.29 3395,3609.98 3300,3704.98 3300,3750.29 3390,3840.29 3460.7,3840.29 H1.16
BBC_DA5: H1.17 U21.2 U27.24 | length 399.2
  Bottom Layer w13: U21.2 3433.94,3553 3433.94,3706.9 3419.78,3721.06 U27.24
BBC_DA6: H1.19 U20.2 U27.22 | length 555.5
  Top Layer w13: v1(3320.89,3484.4) 3338.5,3466.79 3338.5,3465.69 3364.56,3439.63 U20.2@3400.57,3439.63
  Inner3 w13: v1(3224.78,3819.11) 3224.78,3605.5 3320.89,3509.39 v1(3320.89,3484.4)
  Bottom Layer w13: U27.22 3224.78,3894.11 v1(3224.78,3819.11)
BBC_DA7: H1.20 U19.2 U27.21 | length 577.6
  Bottom Layer w13: H1.20 3122.38,3717.82 U19.2@3400.57,3439.63
BBC_DD0: H2.1 U18.2 U27.20 | length 384.9
  Top Layer w13: H2.1 3142.91,3101.97 U18.2
BBC_DD1: H2.2 U17.2 U27.19 | length 337.3
  Bottom Layer w13: U27.19 3219.78,3120.32 3409.76,3310.29 3409.76,3350.43 U17.2
BBC_DD2: H2.4 U16.1 U27.17 | length 172.4
  Top Layer w13: H2.4 3441.65,3101.97 U16.1
BBC_DD3: H2.5 U15.1 U27.16 | length 117.9
  Bottom Layer w13: U27.16 3549.94,3134.98 U15.1
BBC_DD4: H2.6 U14.1 U27.15 | length 113.5
  Top Layer w13: H2.6 3634.94,3114.53 U14.1
BBC_DD5: H2.7 U13.1 U27.14 | length 140.6
  Bottom Layer w13: U13.1 3719.78,3125.41 U27.14
BBC_DD6: H2.9 U12.1 U27.12 | length 247.3
  Top Layer w13: U12.1 3732.95,3210.26 3773.19,3170.02 3854.33,3170.02 H2.9
BBC_DD7: H2.10 U11.1 U27.11 | length 354.6
  Bottom Layer w13: U11.1 3926.5,3210.26 4022.38,3114.38 H2.10
GND: C18.1 C20.1 C21.1 C22.1 C23.2 C26.1 C28.1 C30.2 C31.1 C32.1 C33.2 C35.2 C36.1 C37.1 C38.1 C39.1 C40.1 C41.1 CLNA1.2 CPA1.2 CPA2.2 CPA3.2 CPLL1.2 CRXMX1.2 CTXMX1.2 CVCCCP1.2 CVCO0.2 CVCO1.2 CVCO2.2 CVRXA1.2 CVRXF1.2 CVXTAL1.2 H1.3 pad.50 pad.51 pad.52 pad.53 Q1.2 U1.1 U1.2 U1.3 U1.4 U2.5 U2.7 U2.12 U2.17 U2.31 U2.32 U2.37 U2.42 U2.49 U3.2 U3.26 U3.31 U3.47 U3.49 U4.1 U4.2 U4.3 U4.4 U5.1 U5.2 U5.3 U5.4 U6.1 U6.2 U7.1 U7.2 U27.38 X1.1 X1.2 | length 2176
  Top Layer w12.99: U2.17 3551.75,3531.51 3573.38,3531.51 3576.38,3534.5 v1(3587.1,3534.5) ; v1(3553.96,3641.08) 3570.88,3641.08 U2.12 ; U2.7 3675.16,3600.01 v1(3679.74,3595.43) ; U2.49 3692.87,3500.29 3753.5,3560.93 3753.5,3564.44 3767.84,3578.78 3771.36,3578.78 v1(3788.21,3595.64) ; U2.31 3694.84,3345.45 3710,3330.29 v1(3715,3330.29) 3715,3364.88 U2.32 ; C40.1 v1(3804.94,3238.63) ; U2.37 3818.24,3393.72 3796.7,3393.72 3756.47,3433.95 3756.47,3455.49 3713.44,3498.52 3791.12,3498.52 3799.19,3490.45 U2.42 ; v1(3959.88,3605.19) 3979.37,3585.7 C38.1 ; C37.1 3982.42,3668.34 v1(3982.42,3679.28) ; v1(4142.26,3338.61) 4161.62,3338.61 C21.1 ; C18.1 4205,3273.39 v1(4205,3235.2) ; X1.1@4240,3704.87 X1.1 4257.02,3754.5 v1(4251.32,3760.2) ; C22.1 4274.44,3542.69 4283.86,3542.69 4295.31,3531.24 4295.31,3525.59 4312.16,3508.74 4322.81,3508.74 4338.66,3492.89 4345.1,3492.89 4346.29,3491.71 4365.89,3491.71 U3.31 4369.9,3490.39 4371.16,3489.13 4388.12,3489.13 4395.43,3481.82 4395.43,3464.86 v1(4410,3450.29) ; U3.49 4559.97,3445.29 v1(4600,3445.29) ; U3.2 4663.6,3411.69 v1(4685,3390.29) ; v1(5021.59,3690.29) 5053.97,3657.92 v1(5053.97,3641.34) 5092.92,3680.29 v1(5100,3680.29)
  Top Layer w13: U2.7 3676.84,3633.55 3676.84,3616.28 3684.16,3608.97 3705.52,3608.97 3712.84,3616.28 3712.84,3629.16 3713.55,3629.88 3713.55,3634.25 U2.5 ; v2(4322.37,3610.81) 4325.59,3610.81 4347.55,3588.84 U3.26 ; v1(4420,3410.29) 4504.99,3495.28 U3.49 ; U3.47 4593.6,3384.74 v1(4609.05,3400.19)
  Bottom Layer w12.99: C39.1 C41.1 3739.97,3547.39 3753.5,3560.93 3753.5,3564.44 3767.84,3578.78 3771.36,3578.78 v1(3788.21,3595.64) ; v1(4152.99,3659.78) 4152.99,3669.99 C20.1 ; C23.2 4305.09,3360.19 v1(4320,3345.29) ; v1(4512.68,3781.86) 4524.37,3770.17 CVCO2.2 ; CVCO1.2 4545.31,3461.22 CVCO0.2 4585,3460.29 v1(4600,3445.29)
  other v1: 5290,3055.29 5408.8,3054.74 5180,3075.29 5461.94,3112.15 5125,3120.29 5080,3165.29 5285,3165.29 4870,3180.29 4750,3190.29 4584.49,3192.51 4690,3195.56 5465,3203.38 4420.36,3204.78 4510.04,3204.78 3125,3210.15 3355,3210.29 3450,3210.29 4835,3210.29 5029.07,3211 3960,3235.29 4930.49,3236 4039.72,3237.89 4800,3245.29 4895.95,3279.05 4955.95,3279.05 5017.55,3279.05 5080,3280.29 5388.8,3285.29 3125,3305.29 3255,3305.29 3460,3305.29 5465,3306.25 4825,3310.29 3977.42,3318.19 4770,3330.29 4720,3350.29 4989.07,3354.93 4047.63,3363.51 3977.42,3368.62 4850,3380.29 5053.97,3382.36 5285,3405.29 5465,3409.12 4790,3425.29 4989.07,3431.12 5053.97,3432.36 4830,3455.29 4735,3460.29 3977.42,3466.89 5285,3485.29 4870.98,3490.29 4942.42,3490.29 5004.02,3490.29 5054.02,3490.29 5097.42,3490.29 5465,3500.76 5184.99,3501.95 5393.56,3501.95 4815,3520.29 4705,3525.29 4981.58,3533.34 4760,3540.29 5285,3553.55 4850,3590.29 5053.97,3591.34 4981.58,3596.83 5117.02,3598.94 4684.35,3615.94 5465,3618.52 4745,3630.29 4800,3635.29 3845.51,3662.05 4981.58,3663.38 4845,3670.29 4055,3690.29 4900,3690.29 3255,3700.28 5200,3700.29 5370,3700.29 4770,3710.29 5465,3715.29 5131.24,3735.29 5055,3745.29 4861.76,3750.29 4964.63,3750.29 3979.37,3762.29 3561.57,3766.74 3726.35,3767.55 3824.94,3768.11 4684.18,3775.09 3644.94,3776.74 4605.63,3780.29 4433.84,3782.06 4355,3783.93 3469.41,3794.16 5035,3795.29 5465,3807.93 4257.02,3808.5 5285,3831.65 5100,3855.29 5465,3895.29 5160,3920.29 5235,3950.29 5326.6,3950.29 5412.63,3950.29
RXIN: U2.4 U3.37 | length 1074.1
  Top Layer w13: v2(3728.72,3593.27) 3734.21,3598.77 U2.4 ; v1(4377.57,3326.7) 4377.57,3343.37 U3.37
  Inner3 w13: v2(3728.72,3593.27) 3728.72,3426.57 3759.69,3395.6 4045.31,3395.6 4124.39,3474.68 4327.77,3474.68 4364.19,3438.26 4364.19,3388.13 4385.09,3367.24 4385.09,3354.24 4377.57,3346.71 v1(4377.57,3326.7)
RXIP: U2.3 U3.38 | length 1064.3
  Top Layer w13: U2.3 3753.9,3608.07 v2(3758.69,3603.27) ; v1(4411.61,3326.7) 4416.4,3331.49 U3.38
  Inner3 w13: v2(3758.69,3603.27) 3758.69,3570.33 3753.5,3565.13 3753.5,3563.07 3753.21,3562.78 3753.21,3433.95 3767.56,3419.6 4037.44,3419.6 4111.52,3493.68 4341.61,3493.68 4383.19,3452.1 4383.19,3401 4404.09,3380.11 4404.09,3359.23 4411.61,3351.71 v1(4411.61,3326.7)
RXQN: U2.9 U3.35 | length 891.7
  Top Layer w13: U2.9 3635.79,3603.72 v2(3645.73,3593.77) ; v1(4323.7,3417.19) 4329.2,3411.69 U3.35
  Inner2 w13: v2(3645.73,3593.77) 3645.73,3537.37 3773.82,3409.29 3847.49,3409.29 3852.49,3414.29 4097.07,3414.29 ; 4100,3414.29 4097.07,3414.29 4102.57,3419.78 v2(4132.57,3419.78)
  Inner3 w13: v2(4132.57,3419.78) 4140.65,3411.69 4293.19,3411.69 4298.69,3417.19 v1(4323.7,3417.19)
RXQP: U2.10 U3.36 | length 928.4
  Top Layer w13: v2(3608.39,3593.27) 3615.68,3600.56 3615.68,3634.81 U2.10 ; v1(4323.7,3387.19) 4328.5,3391.99 U3.36
  Inner2 w13: v2(3608.39,3593.27) 3608.39,3590.78 3606.25,3588.63 3606.25,3583.63 3625,3564.88 3625,3531.24 3765.95,3390.29 3855.36,3390.29 3859.86,3394.78 3864.86,3394.78 3865.36,3395.29 4102.07,3395.29 4110.15,3387.21 v2(4132.57,3387.21)
  Inner3 w13: v2(4132.57,3387.21) 4138.05,3392.69 4293.19,3392.69 4298.69,3387.19 v1(4323.7,3387.19)
TXIN: U2.44 U3.44 | length 890.5
  Top Layer w13: v2(3782.98,3524.32) 3788.48,3529.82 U2.44 ; v1(4528.21,3396.23) 4534.51,3389.94 U3.44
  Inner2 w13: v2(3782.98,3524.32) 3783.83,3523.47 3797.22,3523.47 3804.05,3530.3 4014.99,3530.3 4069.85,3475.44 4388.65,3475.44 4388.92,3475.18 4424.94,3475.18 4425.21,3475.44 4467.39,3475.44 4528.21,3414.62 v1(4528.21,3396.23)
TXIP: U2.45 U3.45 | length 931.3
  Top Layer w12.99: U3.45 4554.19,3396.96 v1(4559.55,3402.32)
  Top Layer w13: v2(3782.98,3554.3) 3787.79,3549.5 U2.45
  Inner2 w13: v2(3782.98,3554.3) 3787.98,3549.3 4022.86,3549.3 4077.72,3494.44 4485.82,3494.44 4554.55,3425.7 4554.55,3407.32 v1(4559.55,3402.32)
TXQN: U2.41 U3.42 | length 999.6
  Top Layer w10: v2(3780.95,3474.07) 3784.26,3470.76 U2.41
  Top Layer w13: U3.42 4495.15,3404.35 v1(4498.06,3407.27)
  Inner3 w13: v2(3780.95,3474.07) 3824.93,3474.07 3927.59,3576.72 4439.87,3576.72 4520.15,3496.45 4520.15,3434.36 4498.06,3412.27 v1(4498.06,3407.27)
TXQP: U2.40 U3.43 | length 1064
  Top Layer w10: v2(3780.95,3444.09) 3787.94,3451.08 U2.40
  Top Layer w13: U3.43 4514.85,3325.2 v1(4520,3320.05)
  Inner3 w13: v2(3780.95,3444.09) 3841.82,3444.09 3863.64,3465.91 3863.64,3467.93 3885.49,3489.78 3887.51,3489.78 3955.46,3557.72 4408.42,3557.72 4436.49,3529.65 4436.49,3528.23 4473.57,3491.15 4473.57,3387.08 4487.4,3373.25 4487.4,3332.65 4507.5,3312.55 4512.5,3312.55 v1(4520,3320.05)
pads on no net: U2.38 U6.5 U7.5

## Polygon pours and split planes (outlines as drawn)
GND on Top Layer (solid, pour order 0): 3000,3995.29 5530,3995.29 5530,3015.29 3000,3015.29
GND on Inner3 (solid): 3000,3995.29 5530,3995.29 5530,3015.29 3000,3015.29
GND on Inner2 (solid): 3000,3995.29 5530,3995.29 5530,3015.29 3000,3015.29
GND on Bottom Layer (solid, pour order 2): 3000,3995.29 5530,3995.29 5530,3015.29 3000,3015.29

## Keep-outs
Inner3:
  region: 4314.12,3806.53 4277.75,3842.89 4267.16,3842.89 4264.86,3845.19 4135.25,3845.19 4065.35,3775.29 4060,3775.29 4060,3711.13 4095.42,3675.7 4095.42,3632.59 4115,3613.01 4115,3465.29 4088.35,3438.64 4101.77,3290.77 4288.23,3290.77 4367.2,3369.74 4367.2,3623.29 4314.12,3676.38
GND:
  region: 4045,3775.29 4045,3720.29 4075,3690.29 4075,3649.99 4115,3609.99 4115,3455.29 4085,3425.29 4085,3310.52 4122.84,3272.68 4187.39,3272.68 4220,3305.29 4246.13,3305.29 4261.61,3320.77 4315.48,3320.77 4348.19,3353.48 4348.19,3552.16 4345.96,3554.39 4345.96,3784.33 4290,3840.29 4040,3840.29 4040,3810.29 4045,3805.29 4073.39,3805.29 4073.39,3823.68 4075,3825.29 4274.87,3825.29 4336.05,3764.1 4336.05,3545.29 4340,3545.29 4340,3355.29 4315.33,3330.62 4255.33,3330.62 4250,3325.29 4222.83,3325.29 4197.83,3300.29 4190,3300.29 4174.91,3285.19 4127.69,3285.19 4112.56,3300.33 4112.56,3350.19 4103.08,3359.67 4103.08,3419.27 4102.57,3419.78 4130,3447.21 4130,3615.29 4088.63,3656.66 4088.63,3703.93 4069.26,3723.29 4069.26,3775.29
3.3:
  region: 4695,3960.29 5530,3960.29 5530,3015.29 4695,3015.29
  region: 4314.12,3806.53 4277.75,3842.89 4267.16,3842.89 4264.86,3845.19 4135.25,3845.19 4065.35,3775.29 4060,3775.29 4060,3711.13 4095.42,3675.7 4095.42,3632.59 4115,3613.01 4115,3465.29 4088.35,3438.64 4101.77,3290.77 4288.23,3290.77 4367.2,3369.74 4367.2,3623.29 4314.12,3676.38
Board Outline Layer:
  lines w10: 3025,3099.03 ccw(c3103.74,3099.03) 3103.74,3020.29 5416.26,3020.29 ccw(c5416.26,3099.03) 5495,3099.03 5495,3901.55 ccw(c5416.26,3901.55) 5416.26,3980.29 3103.74,3980.29 ccw(c3103.74,3901.55) 3025,3901.55 3025,3099.03

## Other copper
Top Layer:
  region net GND: 5465,3470.76 cw(c5465,3500.29) 5435.47,3500.29 5435.47,3920.76 5207.23,3920.76 5020.88,3734.41 cw(c5000,3755.29) 5000,3725.76 4829.19,3725.76 4779.63,3676.21 cw(c4758.76,3697.09) 4758.76,3667.56 cw(c4758.76,3697.09) 4729.23,3697.09 cw(c4758.76,3697.09) 4737.88,3717.96 4796.08,3776.17 cw(c4816.96,3755.29) 4816.96,3784.82 4987.77,3784.82 5174.12,3971.17 cw(c5195,3950.29) 5195,3979.82 5450,3979.82 cw(c5450,3950.29) 5470.88,3971.17 5485.88,3956.17 cw(c5465,3935.29) 5494.53,3935.29 5494.53,3500.29 cw(c5465,3500.29)
  region net GND: 5195,3020.76 cw(c5195,3050.29) 5174.12,3029.41 4987.77,3215.76 4816.96,3215.76 cw(c4816.96,3245.29) 4796.08,3224.41 4737.88,3282.61 cw(c4758.76,3303.49) 4729.23,3303.49 cw(c4758.76,3303.49) 4758.76,3333.02 cw(c4758.76,3303.49) 4779.63,3324.37 4829.19,3274.82 5000,3274.82 cw(c5000,3245.29) 5020.88,3266.17 5207.23,3079.82 5435.47,3079.82 5435.47,3500.29 cw(c5465,3500.29) 5465,3529.82 cw(c5465,3500.29) 5494.53,3500.29 5494.53,3065.29 cw(c5465,3065.29) 5485.88,3044.41 5470.88,3029.41 cw(c5450,3050.29) 5450,3020.76
  region net GND: 4365,3135.29 4379.19,3135.29 4379.19,3058.58 4365,3058.58
  region net GND: 4403.93,3157.63 4440,3157.63 4440,3145.29 4403.93,3145.29
  region net GND: 4494.66,3157.63 4550,3157.63 4550,3145.29 4494.66,3145.29
  region net GND: 4584.61,3157.63 4655,3157.63 4655,3145.29 4584.61,3145.29
  region net GND: 4690,3152.63 4770,3152.63 4770,3145.29 4690,3145.29
Bottom Layer:
  region net GND: 5470,3469.83 cw(c5470,3499.36) 5440.47,3499.36 5440.47,3863.06 5392.77,3910.76 5172.23,3910.76 5139.53,3878.06 5139.53,3840.29 cw(c5110,3840.29) 5130.88,3819.41 5110.88,3799.41 cw(c5090,3820.29) 5090,3790.76 cw(c5090,3820.29) 5060.47,3820.29 cw(c5090,3820.29) 5069.12,3841.17 5080.47,3852.52 5080.47,3890.29 cw(c5110,3890.29) 5089.12,3911.17 5139.12,3961.17 cw(c5160,3940.29) 5160,3969.82 5405,3969.82 cw(c5405,3940.29) 5425.88,3961.17 5490.88,3896.17 cw(c5470,3875.29) 5499.53,3875.29 5499.53,3499.36 cw(c5470,3499.36)
  region net GND: 5160,3025.53 cw(c5160,3055.06) 5139.12,3034.18 5089.12,3084.18 cw(c5110,3105.06) 5080.47,3105.06 5080.47,3142.83 5069.12,3154.18 cw(c5090,3175.06) 5060.47,3175.06 cw(c5090,3175.06) 5090,3204.59 cw(c5090,3175.06) 5110.88,3195.94 5130.88,3175.94 cw(c5110,3155.06) 5139.53,3155.06 5139.53,3117.29 5172.23,3084.59 5392.77,3084.59 5440.47,3132.29 5440.47,3495.99 cw(c5470,3495.99) 5470,3525.52 cw(c5470,3495.99) 5499.53,3495.99 5499.53,3120.06 cw(c5470,3120.06) 5490.88,3099.18 5425.88,3034.18 cw(c5405,3055.06) 5405,3025.53

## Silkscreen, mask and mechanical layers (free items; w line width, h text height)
Top Silkscreen Layer:
  text "TX" at 5235,3835.29 h78.74
  text "OpenBeam: PAE v1" at 3110,3745.29 h78.74
  text "RX" at 5215,3075.29 h78.74
Bottom Silkscreen Layer:
  text "Up/Down Converter" at 4640,3235.29 h39.37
